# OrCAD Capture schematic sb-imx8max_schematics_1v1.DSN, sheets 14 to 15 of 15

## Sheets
14 08. UART,RS232,RS485, EEPROM,SD: size C; title: 08. UART,RS232,RS485, EEPROM,SD; note: 8010055003
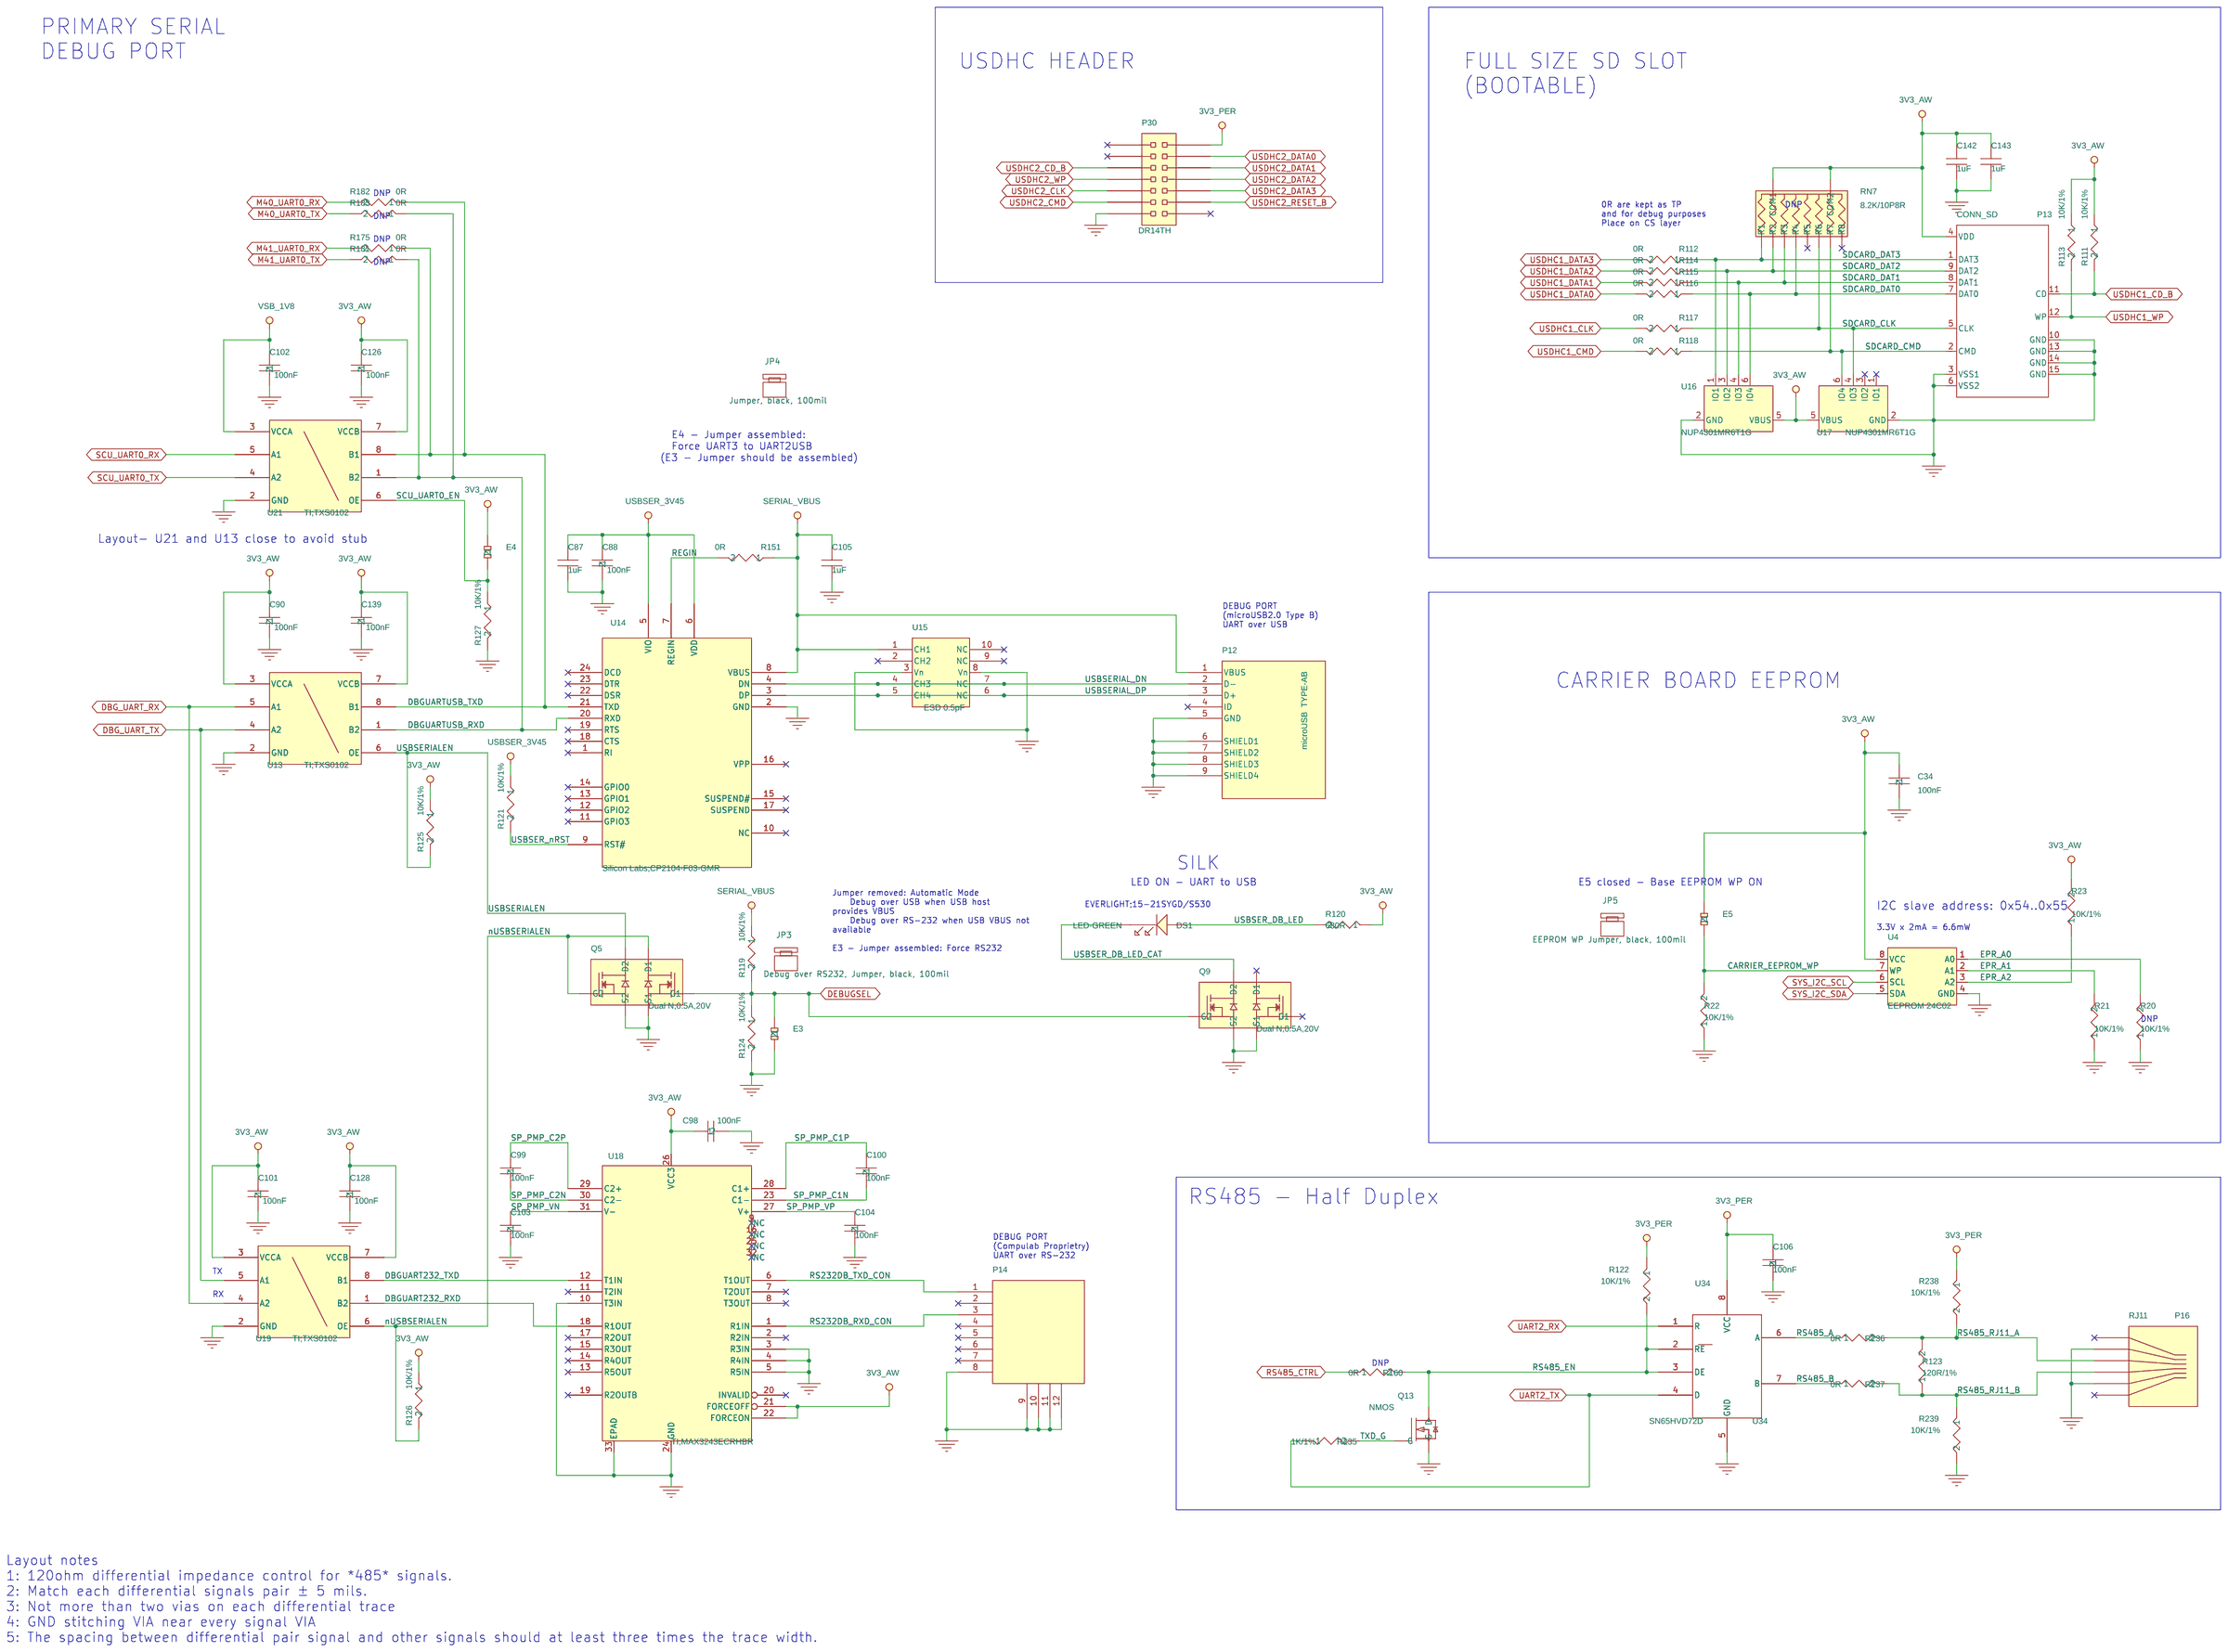
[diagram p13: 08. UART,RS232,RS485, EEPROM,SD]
15 09. POWER: size B; title: 09. POWER; note: 8010055003
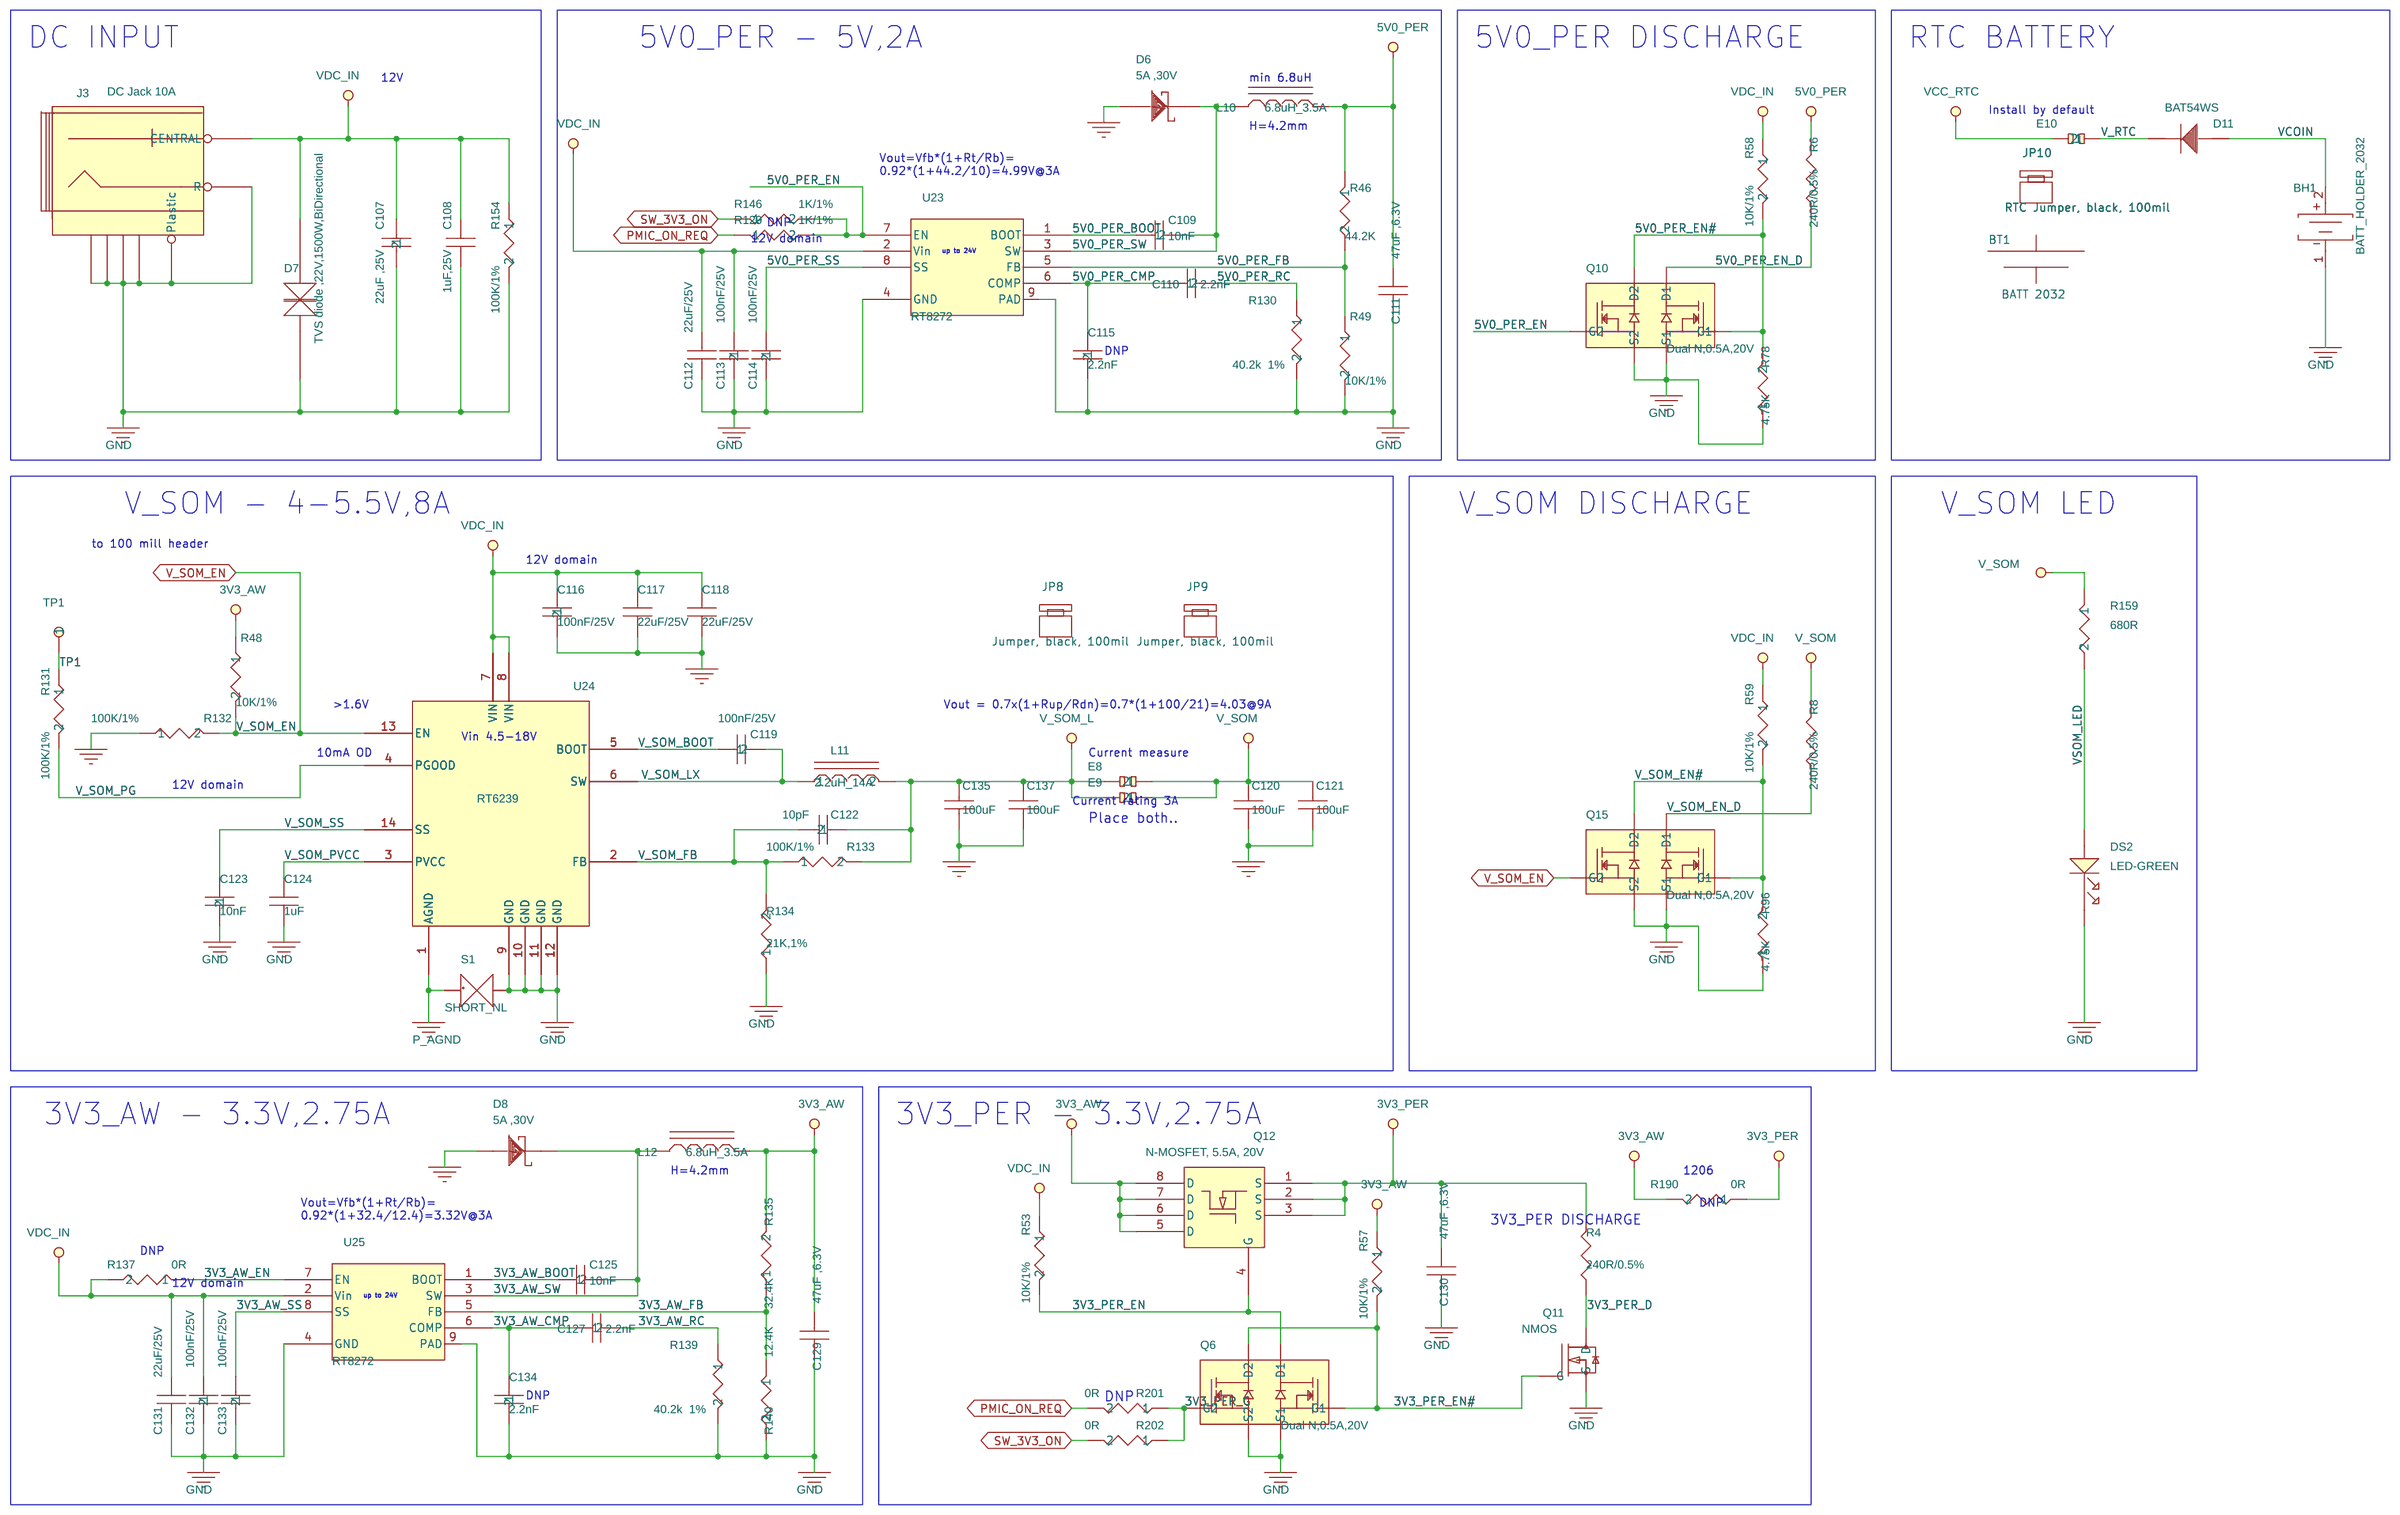
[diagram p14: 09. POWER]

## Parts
sheet 08. UART,RS232,RS485, EEPROM,SD
C34  100nF  [RC0402]
C87  1uF  [RC0402]
C88  100nF  [RC0402]
C90  100nF  [RC0402]
C98  100nF  [RC0402]
C99  100nF  [RC0402]
C100  100nF  [RC0402]
C101  100nF  [RC0402]
C102  100nF  [RC0402]
C103  100nF  [RC0402]
C104  100nF  [RC0402]
C105  1uF  [RC0402]
C106  100nF  [RC0402]
C126  100nF  [RC0402]
C128  100nF  [RC0402]
C139  100nF  [RC0402]
C142  1uF  [RC0402]
C143  1uF  [RC0402]
DS1  LED-GREEN  [LED-1206]
E3  HDR1X2  [1X2THHDR]
E4  HDR1X2  [1X2THHDR]
E5  HDR1X2  [1X2THHDR]
JP3  Debug over RS232, Jumper, black, 100mil
JP4  Jumper, black, 100mil
JP5  EEPROM WP Jumper, black, 100mil
P12  microUSB  TYPE-AB  [MICRO-USB-AB-RA-SM]
P13  CONN_SD  [SD-RA-SM]
P14  Ultra Mini Serial Connector  [UMS-8]
P16  RJ11  [RJ11TH6-6]
P30  DR14TH  [2X7THHDR]
Q5  Dual N,0.5A,20V  [SOT-563-6]
Q9  Dual N,0.5A,20V  [SOT-563-6]
Q13  NMOS  [SOT23]
R20  10K/1%  [RC0402]
R21  10K/1%  [RC0402]
R22  10K/1%  [RC0402]
R23  10K/1%  [RC0402]
R111  10K/1%  [RC0402]
R112  0R  [RC0402]
R113  10K/1%  [RC0402]
R114  0R  [RC0402]
R115  0R  [RC0402]
R116  0R  [RC0402]
R117  0R  [RC0402]
R118  0R  [RC0402]
R119  10K/1%  [RC0402]
R120  680R  [RC0402]
R121  10K/1%  [RC0402]
R122  10K/1%  [RC0402]
R123  120R/1%  [RC0603]
R124  10K/1%  [RC0402]
R125  10K/1%  [RC0402]
R126  10K/1%  [RC0402]
R127  10K/1%  [RC0402]
R151  0R  [RC0402]
R160  0R  [RC0402]
R175  0R  [RC0402]
R181  0R  [RC0402]
R182  0R  [RC0402]
R183  0R  [RC0402]
R235  1K/1%  [RC0402]
R236  0R  [RC0402]
R237  0R  [RC0402]
R238  10K/1%  [RC0402]
R239  10K/1%  [RC0402]
RN7  8.2K/10P8R  [RESNET10P1206]
U4  EEPROM 24C02  [MO-229VCED-2]
U13  TI;TXS0102  [MO-187DA-8]
U14  Silicon Labs;CP2104-F03-GMR  [MO-220VGGD-8]
U15  ESD 0.5pF  [DFN-X2510D-10]
U16  NUP4301MR6T1G  [SOT23-6L]
U17  NUP4301MR6T1G  [SOT23-6L]
U18  TI;MAX3243ECRHBR  [QFN5x5-32]
U19  TI;TXS0102  [MO-187DA-8]
U21  TI;TXS0102  [MO-187DA-8]
U34  SN65HVD72D  [MSOP-8]
sheet 09. POWER
BH1  BATT_HOLDER_2032  [BATTH20MM]
BT1  BATT 2032
C107  22uF ,25V  [C1210H1_9]
C108  1uF,25V  [RC0402]
C109  10nF  [RC0402]
C110  2.2nF  [RC0402]
C111  47uF ,6.3V  [C0805]
C112  22uF/25V  [C0805]
C113  100nF/25V  [RC0402]
C114  100nF/25V  [RC0402]
C115  2.2nF  [RC0402]
C116  100nF/25V  [RC0402]
C117  22uF/25V  [C0805]
C118  22uF/25V  [C0805]
C119  100nF/25V  [RC0402]
C120  100uF  [C1210H2_5]
C121  100uF  [C1210H2_5]
C122  10pF  [RC0402]
C123  10nF  [RC0402]
C124  1uF  [RC0402]
C125  10nF  [RC0402]
C127  2.2nF  [RC0402]
C129  47uF ,6.3V  [C0805]
C130  47uF ,6.3V  [C0805]
C131  22uF/25V  [C0805]
C132  100nF/25V  [RC0402]
C133  100nF/25V  [RC0402]
C134  2.2nF  [RC0402]
C135  100uF  [C1210H2_5]
C137  100uF  [C1210H2_5]
D6  5A ,30V  [SOD-128]
D7  TVS diode ,22V,1500W,BiDirectional  [DO-214AB]
D8  5A ,30V  [SOD-128]
D11  BAT54WS  [SOD-323]
DS2  LED-GREEN  [LED-1206]
E8  HDR1X2  [1X2THHDR]
E9  HDR1X2  [1X2THHDR]
E10  HDR1X2  [1X2THHDR]
J3  DC Jack 10A  [PJ-0810-TH]
JP8  Jumper, black, 100mil
JP9  Jumper, black, 100mil
JP10  RTC Jumper, black, 100mil
L10  6.8uH_3.5A  [IND8_2x8_2]
L11  2.2uH_14A  [IND7x7_2SM]
L12  6.8uH_3.5A  [IND8_2x8_2]
Q6  Dual N,0.5A,20V  [SOT-563-6]
Q10  Dual N,0.5A,20V  [SOT-563-6]
Q11  NMOS  [SOT23]
Q12  N-MOSFET, 5.5A, 20V  [PowerpakSO-8]
Q15  Dual N,0.5A,20V  [SOT-563-6]
R4  240R/0.5%  [RC0402]
R6  240R/0.5%  [RC0402]
R8  240R/0.5%  [RC0402]
R46  44.2K  [RC0402]
R48  10K/1%  [RC0402]
R49  10K/1%  [RC0402]
R53  10K/1%  [RC0402]
R57  10K/1%  [RC0402]
R58  10K/1%  [RC0402]
R59  10K/1%  [RC0402]
R78  4.75K  [RC0402]
R96  4.75K  [RC0402]
R129  1K/1%  [RC0402]
R130  40.2k  1%  [RC0402]
R131  100K/1%  [RC0402]
R132  100K/1%  [RC0402]
R133  100K/1%  [RC0402]
R134  21K,1%  [RC0402]
R135  32.4K  [RC0402]
R137  0R  [RC0402]
R139  40.2k  1%  [RC0402]
R140  12.4K  [RC0402]
R146  1K/1%  [RC0402]
R154  100K/1%  [RC0402]
R159  680R  [RC0402]
R190  0R  [RC1206]
R201  0R  [RC0402]
R202  0R  [RC0402]
S1  SHORT_NL  [SHORT_NL]
TP1  TESTPOINT  [TESTPOINT]
U23  RT8272  [PSOP-8-2X2]
U24  RT6239  [uQFN2x3-14]
U25  RT8272  [PSOP-8-2X2]

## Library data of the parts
C34 = 100nF,_10V,_X7R,_10%,_0402_5: CLABCONF0: SB-iMX8MAX
C87 C105 C142 C143 = 1uF,X5R,6.3V,0402: CLABCONF0: SB-iMX8MAX
C88 = 100nF,_10V,_X7R,_10%,_0402_12: CLABCONF0: SB-iMX8MAX
C90 = 100nF,_10V,_X7R,_10%,_0402_3: CLABCONF0: SB-iMX8MAX
C98 = 100nF,_10V,_X7R,_10%,_0402_2: CLABCONF0: SB-iMX8MAX
C99 = 100nF,_10V,_X7R,_10%,_0402_9: CLABCONF0: SB-iMX8MAX
C100 = 100nF,_10V,_X7R,_10%,_0402_4: CLABCONF0: SB-iMX8MAX
C101 = 100nF,_10V,_X7R,_10%,_0402_7: CLABCONF0: SB-iMX8MAX
C102 = 100nF,_10V,_X7R,_10%,_0402_8: CLABCONF0: SB-iMX8MAX
C103 = 100nF,_10V,_X7R,_10%,_0402: CLABCONF0: SB-iMX8MAX
C104 = 100nF,_10V,_X7R,_10%,_0402_6: CLABCONF0: SB-iMX8MAX
C106 = 100nF,_10V,_X7R,_10%,_0402_13: CLABCONF0: SB-iMX8MAX
C126 = 100nF,_10V,_X7R,_10%,_0402_10: CLABCONF0: SB-iMX8MAX
C128 = 100nF,_10V,_X7R,_10%,_0402_11: CLABCONF0: SB-iMX8MAX
C139 = 100nF,_10V,_X7R,_10%,_0402_1: CLABCONF0: SB-iMX8MAX
DS1 DS2 = LED-GREEN_1206_3: CLABCONF0: SB-iMX8MAX
E3 E9 = HDR_1x2_100MIL_TH_JUMPER_2: CLABCONF0: SB-iMX8MAX
E4 E10 = HDR_1x2_100MIL_TH_JUMPER_1: CLABCONF0: SB-iMX8MAX
E5 E8 = HDR_1x2_100MIL_TH_JUMPER: CLABCONF0: SB-iMX8MAX
JP3-JP5 JP8 JP9 = Jumper,_black,_100mil_0: CLABCONF0: SB-iMX8MAX
P12 = Conn.,_Micro-USB,_B-Type: CLABCONF0: SB-iMX8MAX; P/N: 180K00501S
P13 = SDIO_SLOT: CLABCONF0: SB-iMX8MAX
P14 = Ultra_Mini_Serial_Connector: CLABCONF0: SB-iMX8MAX
P16 = RJ11: CLABCONF0: SB-iMX8MAX
P30 = HDR_2x7_100MIL_TH: CLABCONF0: SB-iMX8MAX; P/N: 190C01402
Q5 Q6 Q9 Q10 Q15 = DUAL_N-MOSFET,_0.5A_20V: CLABCONF0: SB-iMX8MAX
Q11 Q13 = N-MOSFET,NDS335N,100mOhm@2.5V: CLABCONF0: SB-iMX8MAX
R20 = 10K,1%,0402,1_16W_14: CLABCONF0: DNP
R21 = 10K,1%,0402,1_16W_8: CLABCONF0: SB-iMX8MAX
R22 = 10K,1%,0402,1_16W_12: CLABCONF0: SB-iMX8MAX
R23 = 10K,1%,0402,1_16W_10: CLABCONF0: SB-iMX8MAX
R111 = 10K,1%,0402,1_16W_11: CLABCONF0: SB-iMX8MAX
R112 = 0R,_0402_1_11: CLABCONF0: SB-iMX8MAX
R59 R113 = 10K,1%,0402,1_16W_5: CLABCONF0: SB-iMX8MAX
R114 = 0R,_0402_1_8: CLABCONF0: SB-iMX8MAX
R115 R202 = 0R,_0402_1: CLABCONF0: SB-iMX8MAX
R116 = 0R,_0402_1_4: CLABCONF0: SB-iMX8MAX
R117 = 0R,_0402_1_3: CLABCONF0: SB-iMX8MAX
R118 = 0R,_0402_1_9: CLABCONF0: SB-iMX8MAX
R48 R119 = 10K,1%,0402,1_16W: CLABCONF0: SB-iMX8MAX
R120 R159 = 47K,_0402: CLABCONF0: SB-iMX8MAX; P/N: 161C68001S
R49 R121 = 10K,1%,0402,1_16W_1: CLABCONF0: SB-iMX8MAX
R57 R122 = 10K,1%,0402,1_16W_2: CLABCONF0: SB-iMX8MAX
R123 = 120R_1%,_0603: CLABCONF0: SB-iMX8MAX
R58 R124 = 10K,1%,0402,1_16W_3: CLABCONF0: SB-iMX8MAX
R125 = 10K,1%,0402,1_16W_9: CLABCONF0: SB-iMX8MAX
R126 = 10K,1%,0402,1_16W_15: CLABCONF0: SB-iMX8MAX
R127 = 10K,1%,0402,1_16W_6: CLABCONF0: SB-iMX8MAX
R151 = 0R,_0402_1_6: CLABCONF0: SB-iMX8MAX
R137 R160 = 0R,_0402_1_2: CLABCONF0: DNP
R175 = 0R,_0402_1_5: CLABCONF0: DNP
R181 = 0R,_0402_1_7: CLABCONF0: DNP
R182 = 0R,_0402_1_10: CLABCONF0: DNP
R183 = 0R,_0402_1_12: CLABCONF0: DNP
R235 = 10K,1%,0402,1_16W_13: CLABCONF0: SB-iMX8MAX; P/N: 161C10011S
R236 = 0R,_0402_1_13: CLABCONF0: SB-iMX8MAX
R237 = 0R,_0402_1_1: CLABCONF0: SB-iMX8MAX
R53 R238 = 10K,1%,0402,1_16W_4: CLABCONF0: SB-iMX8MAX
R239 = 10K,1%,0402,1_16W_7: CLABCONF0: SB-iMX8MAX
RN7 = RN,8.2K,10P8R@1206: CLABCONF0: DNP
U4 = 24C02,_serial_EE,_2KB,_I2C: CLABCONF0: SB-iMX8MAX; P/N: 111S30801S
U13 U19 U21 = TXS0102_0: CLABCONF0: SB-iMX8MAX; P/N: 116A01020S
U14 = CP2104_0: CLABCONF0: SB-iMX8MAX; P/N: 116A00140S
U15 = IC,ESD_Diode,0.25pF_,x4: CLABCONF0: SB-iMX8MAX; P/N: 132D10020S
U16 U17 = IP4220CZ6_0: CLABCONF0: SB-iMX8MAX
U18 = MAX3243E_RS-232_3T5R_BGA: CLABCONF0: SB-iMX8MAX
U34 = SN65HVD72D_1: CLABCONF0: SB-iMX8MAX; P/N: 116A00310S; PN: 116A00310S
BH1 = BATT_HOLDER_0: CLABCONF0: SB-iMX8MAX
BT1 = BATT_2032: CLABCONF0: SB-iMX8MAX
C107 = Cap.,_47uF,_16V,_X5R: CLABCONF0: SB-iMX8MAX; P/N: 151C22620S
C108 = 1uF,16V,0402: CLABCONF0: SB-iMX8MAX; P/N: 151C10501S
C109 = 10nF,_25V,_X7R,_10%,_0402_2: CLABCONF0: SB-iMX8MAX
C110 = 2.2nF,_50V,_X7R,_10%,_0402_3: CLABCONF0: SB-iMX8MAX
C111 = 47uF,6.3V,X5R: CLABCONF0: SB-iMX8MAX
C112 = Cap.,22uF,25V,_0805_1: CLABCONF0: SB-iMX8MAX
C113 = 100nF_0402_25V_2: CLABCONF0: SB-iMX8MAX
C114 = 100nF_0402_25V: CLABCONF0: SB-iMX8MAX
C115 = 2.2nF,_50V,_X7R,_10%,_0402: CLABCONF0: DNP
C116 = 100nF_0402_25V_5: CLABCONF0: SB-iMX8MAX
C117 = 22uF,25V,_0805_1: CLABCONF0: SB-iMX8MAX
C118 = 22uF,25V,_0805: CLABCONF0: SB-iMX8MAX
C119 = 100nF_0402_25V_4: CLABCONF0: SB-iMX8MAX
C120 C121 C135 C137 = 100uF,_6.3V,_X5R,_20%,_1206: CLABCONF0: SB-iMX8MAX
C122 = 10pF,50V,NPO,_5%,_0402: CLABCONF0: SB-iMX8MAX
C123 = 10nF,_25V,_X7R,_10%,_0402: CLABCONF0: SB-iMX8MAX
C124 = 1uF,16V,0402: CLABCONF0: SB-iMX8MAX
C125 = 10nF,_25V,_X7R,_10%,_0402_1: CLABCONF0: SB-iMX8MAX
C127 = 2.2nF,_50V,_X7R,_10%,_0402_1: CLABCONF0: SB-iMX8MAX
C129 = 47uF,6.3V,X5R_1: CLABCONF0: SB-iMX8MAX
C130 = 47uF,6.3V,X5R_2: CLABCONF0: SB-iMX8MAX
C131 = Cap.,22uF,25V,_0805: CLABCONF0: SB-iMX8MAX
C132 = 100nF_0402_25V_1: CLABCONF0: SB-iMX8MAX
C133 = 100nF_0402_25V_3: CLABCONF0: SB-iMX8MAX
C134 = 2.2nF,_50V,_X7R,_10%,_0402_2: CLABCONF0: DNP
D6 D8 = Diode_Shotky,5A,30V: CLABCONF0: SB-iMX8MAX
D7 = Diode_,TVS_,15V,1500W_1: CLABCONF0: SB-iMX8MAX; P/N: 132D10030S
D11 = BAT54WS_0: CLABCONF0: SB-iMX8MAX
J3 = DC_Jack_,5.5_2_0.5,10A,20V: CLABCONF0: SB-iMX8MAX
JP10 = Jumper,_black,_100mil: CLABCONF0: SB-iMX8MAX
L10 L12 = IND_6.8uH_3.5A: CLABCONF0: SB-iMX8MAX; P/N: 147A6R801S
L11 = IND_DELTA_MPL73-2R2_2.2uH_14A: CLABCONF0: SB-iMX8MAX
Q12 = N-MOSFET_5_0.5A_@20V_Vgs: CLABCONF0: SB-iMX8MAX
R4 = 240R_resistor,_%0.5: CLABCONF0: SB-iMX8MAX; P/N: 161C24003S
R6 = 240R_resistor,_%0.5_1: CLABCONF0: SB-iMX8MAX; P/N: 161C24003S
R8 = 240R_resistor,_%0.5_2: CLABCONF0: SB-iMX8MAX; P/N: 161C24003S
R46 = 100K,_0402: CLABCONF0: SB-iMX8MAX; P/N: 161C44221S
R78 = 4_0.75K,1%,0402,1_16W_1: CLABCONF0: SB-iMX8MAX
R96 = 4_0.75K,1%,0402,1_16W: CLABCONF0: SB-iMX8MAX
R129 = 1K,1%,0402,1_16W: CLABCONF0: DNP; Group: CAN
R130 = 40.2k_,1%: CLABCONF0: SB-iMX8MAX
R131 = 100K,_1%,_0402,_1_16W: CLABCONF0: SB-iMX8MAX
R132 = 100K,_1%,_0402,_1_16W_3: CLABCONF0: SB-iMX8MAX
R133 = 100K,_1%,_0402,_1_16W_1: CLABCONF0: SB-iMX8MAX
R134 = 43.2K,1%,0402: CLABCONF0: SB-iMX8MAX; P/N: 161C21021S
R135 = 32.4K,_0402: CLABCONF0: SB-iMX8MAX; P/N: 161C32421S
R139 = 40.2k_,1%_1: CLABCONF0: SB-iMX8MAX
R140 = 4.99K,1%,0402,1_16W: CLABCONF0: SB-iMX8MAX; P/N: 161C12421S
R146 = 1K,1%,0402,1_16W_1: CLABCONF0: SB-iMX8MAX; Group: CAN
R154 = 100K,_1%,_0402,_1_16W_2: CLABCONF0: SB-iMX8MAX
R190 = 0R,_1206: CLABCONF0: DNP
R201 = 0R,_0402_1_1: CLABCONF0: DNP
S1 = MISC_SHORT_NL: CLABCONF0: SB-iMX8MAX
TP1 = TESTPOINT: CLABCONF0: SB-iMX8MAX
U23 U25 = RT8272,Converter,3A,24V: CLABCONF0: SB-iMX8MAX
U24 = RT6239A_B: CLABCONF0: SB-iMX8MAX; P/N: 123V08000S

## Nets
3V3_AW: C34.1 C90.1 C98.1 C101.1 C126.1 C128.1 C129.1 C139.1 C142.1 C143.1 E4.1 E5.1 L12.2 P13.4(VDD) Q12.5(D) Q12.6(D) Q12.7(D) Q12.8(D) R23.2 R48.1 R57.1 R111.1 R113.1 R120.1 R125.1 R126.1 R135.2 R190.2 RN7.5(COM1) RN7.10(COM2) U4.8(VCC) U13.3(VCCA) U13.7(VCCB) U16.5(VBUS) U17.5(VBUS) U18.21(FORCEOFF) U18.22(FORCEON) U18.26(VCC3) U19.3(VCCA) U19.7(VCCB) U21.7(VCCB) ; also on sheet 5 9 11 12 13
3V3_AW_BOOT: C125.1 U25.1(BOOT)
3V3_AW_CMP: C127.1 C134.1 U25.6(COMP)
3V3_AW_EN: R137.1 U25.7(EN)
3V3_AW_FB: R135.1 R140.1 U25.5(FB)
3V3_AW_RC: C127.2 R139.1
3V3_AW_SS: C133.1 U25.8(SS)
3V3_AW_SW: C125.2 D8.CATHODE L12.1 U25.3(SW)
3V3_PER: C106.1 C130.1 P30.2 Q12.1(S) Q12.2(S) Q12.3(S) R4.1 R122.1 R190.1 R238.1 U34.8(VCC) ; also on sheet 1 2 3 4 5 6 9 11 12 13
3V3_PER_D: Q11.3(D) R4.2
3V3_PER_EN: Q6.6(D1) Q12.4(G) R53.2
3V3_PER_EN#: Q6.2(G1) Q6.3(D2) Q11.1(G) R57.2
3V3_PER_G: Q6.5(G2) R201.1 R202.1
5V0_PER: C111.1 L10.2 R6.1 R46.1 ; also on sheet 1 4 9 11 12 13
5V0_PER_BOOT: C109.1 U23.1(BOOT)
5V0_PER_CMP: C110.1 C115.1 U23.6(COMP)
5V0_PER_EN: Q10.5(G2) R129.2 R146.2 U23.7(EN)
5V0_PER_EN#: Q10.2(G1) Q10.3(D2) R58.2 R78.2
5V0_PER_EN_D: Q10.6(D1) R6.2
5V0_PER_FB: R46.2 R49.1 U23.5(FB)
5V0_PER_RC: C110.2 R130.1
5V0_PER_SS: C114.1 U23.8(SS)
5V0_PER_SW: C109.2 D6.CATHODE L10.1 U23.3(SW)
GND: BH1.1(MINUS) C34.2 C87.2 C88.2 C90.2 C98.2 C101.2 C102.2 C103.2 C104.2 C105.2 C106.2 C107.2 C108.2 C111.2 C112.2 C113.2 C114.2 C115.2 C116.2 C117.2 C118.2 C120.1 C121.1 C123.2 C124.2 C126.2 C128.2 C129.2 C130.2 C131.2 C132.2 C133.2 C134.2 C135.1 C137.1 C139.2 C142.2 C143.2 D6.ANODE D7.ANODE D8.ANODE DS2.CATHODE E3.2 J3.2(R) J3.3(Plastic) J3.SH1 J3.SH2 J3.SH3 J3.SH4 P12.5(GND) P12.6(SHIELD1) P12.7(SHIELD2) P12.8(SHIELD3) P12.9(SHIELD4) P13.3(VSS1) P13.6(VSS2) P13.10(GND) P13.13(GND) P13.14(GND) P13.15(GND) P14.8 P14.9(CHASSIS) P14.10(CHASSIS) P14.11(CHASSIS) P14.12(CHASSIS) P16.2 P16.5 P30.13 Q5.1(S1) Q5.4(S2) Q6.1(S1) Q6.4(S2) Q9.1(S1) Q9.4(S2) Q10.1(S1) Q10.4(S2) Q11.2(S) Q13.2(S) Q15.1(S1) Q15.4(S2) R20.1 R21.1 R22.1 R49.2 R78.1 R96.1 R124.2 R127.2 R130.2 R132.1 R134.1 R139.2 R140.2 R154.2 R239.2 S1.2 U4.4(GND) U13.2(GND) U14.2(GND) U15.3(Vn) U15.8(Vn) U16.2(GND) U17.2(GND) U18.3(R3IN) U18.4(R4IN) U18.5(R5IN) U18.10(T3IN) U18.24(GND) U18.33(EPAD) U19.2(GND) U21.2(GND) U23.4(GND) U23.9(PAD) U24.9(GND) U24.10(GND) U24.11(GND) U24.12(GND) U25.4(GND) U25.9(PAD) U34.5(GND) ; also on sheet 1 2 3 4 5 6 7 9 10 11 12 13
VCC_RTC: E10.2 ; also on sheet 9
CARRIER_EEPROM_WP: E5.2 R22.2 U4.7(WP)
DBG_UART_RX: U13.5(A1) U19.4(A2) ; also on sheet 9
DBG_UART_TX: U13.4(A2) U19.5(A1) ; also on sheet 9
DBGUART232_RXD: U18.18(R1OUT) U19.1(B2)
DBGUART232_TXD: U18.12(T1IN) U19.8(B1)
DBGUARTUSB_RXD: R181.1 R183.1 U13.1(B2) U14.20(RXD) U21.1(B2)
DBGUARTUSB_TXD: R175.1 R182.1 U13.8(B1) U14.21(TXD) U21.8(B1)
DEBUGSEL: E3.1 Q5.2(G1) Q9.5(G2) R119.2 R124.1 ; also on sheet 13
EPR_A0: R20.2 U4.1(A0)
EPR_A1: R21.2 U4.2(A1)
EPR_A2: R23.1 U4.3(A2)
M40_UART0_RX: R182.2 ; also on sheet 9
M40_UART0_TX: R183.2 ; also on sheet 9
M41_UART0_RX: R175.2 ; also on sheet 9
M41_UART0_TX: R181.2 ; also on sheet 9
nUSBSERIALEN: Q5.5(G2) Q5.6(D1) R126.2 U19.6(OE)
P_AGND: S1.1 U24.1(AGND)
PMIC_ON_REQ: R129.1 R201.2 ; also on sheet 9 12 13
REGIN: R151.2 U14.7(REGIN)
RS232DB_RXD_CON: P14.3 U18.1(R1IN)
RS232DB_TXD_CON: P14.1 U18.6(T1OUT)
RS485_A: R236.1 U34.6(A)
RS485_B: R237.1 U34.7(B)
RS485_CTRL: R160.1 ; also on sheet 13
RS485_EN: Q13.3(D) R122.2 R160.2 U34.2(RE) U34.3(DE)
RS485_RJ11_A: P16.3 R123.2 R236.2 R238.2
RS485_RJ11_B: P16.4 R123.1 R237.2 R239.1
SCU_UART0_EN: E4.2 R127.1 U21.6(OE)
SCU_UART0_RX: U21.5(A1) ; also on sheet 9 12
SCU_UART0_TX: U21.4(A2) ; also on sheet 9 12
SDCARD_CLK: P13.5(CLK) R117.1 RN7.7(R6) U17.4(IO3)
SDCARD_CMD: P13.2(CMD) R118.1 RN7.8(R7) U17.6(IO4)
SDCARD_DAT0: P13.7(DAT0) R116.1 RN7.4(R4) U16.6(IO4)
SDCARD_DAT1: P13.8(DAT1) R115.1 RN7.3(R3) U16.4(IO3)
SDCARD_DAT2: P13.9(DAT2) R114.1 RN7.2(R2) U16.3(IO2)
SDCARD_DAT3: P13.1(DAT3) R112.1 RN7.1(R1) U16.1(IO1)
SERIAL_VBUS: C105.1 P12.1(VBUS) R119.1 R151.1 U14.8(VBUS) U15.1(CH1)
SP_PMP_C1N: C100.2 U18.23(C1-)
SP_PMP_C1P: C100.1 U18.28(C1+)
SP_PMP_C2N: C99.2 U18.30(C2-)
SP_PMP_C2P: C99.1 U18.29(C2+)
SP_PMP_VN: C103.1 U18.31(V-)
SP_PMP_VP: C104.1 U18.27(V+)
SW_3V3_ON: R146.1 R202.2 ; also on sheet 9
SYS_I2C_SCL: U4.6(SCL) ; also on sheet 2 5 9 11 13
SYS_I2C_SDA: U4.5(SDA) ; also on sheet 2 5 9 11 13
TP1: R131.1 TP1.1
TXD_G: Q13.1(G) R235.2
UART2_RX: U34.1(R) ; also on sheet 9
UART2_TX: R235.1 U34.4(D) ; also on sheet 9
USBSER_3V45: C87.1 C88.1 R121.1 U14.5(VIO) U14.6(VDD)
USBSER_DB_LED: DS1.ANODE R120.2
USBSER_DB_LED_CAT: DS1.CATHODE Q9.3(D2)
USBSER_nRST: R121.2 U14.9(RST#)
USBSERIAL_DN: P12.2(D-) U14.4(DN) U15.4(CH3) U15.7(NC)
USBSERIAL_DP: P12.3(D+) U14.3(DP) U15.5(CH4) U15.6(NC)
USBSERIALEN: Q5.3(D2) R125.2 U13.6(OE)
USDHC1_CD_B: P13.11(CD) R111.2 ; also on sheet 9
USDHC1_CLK: R117.2 ; also on sheet 9
USDHC1_CMD: R118.2 ; also on sheet 9
USDHC1_DATA0: R116.2 ; also on sheet 9
USDHC1_DATA1: R115.2 ; also on sheet 9
USDHC1_DATA2: R114.2 ; also on sheet 9
USDHC1_DATA3: R112.2 ; also on sheet 9
USDHC1_WP: P13.12(WP) R113.2 ; also on sheet 9
USDHC2_CD_B: P30.5 ; also on sheet 9
USDHC2_CLK: P30.9 ; also on sheet 9
USDHC2_CMD: P30.11 ; also on sheet 9
USDHC2_DATA0: P30.4 ; also on sheet 9
USDHC2_DATA1: P30.6 ; also on sheet 9
USDHC2_DATA2: P30.8 ; also on sheet 9
USDHC2_DATA3: P30.10 ; also on sheet 9
USDHC2_RESET_B: P30.12 ; also on sheet 9 12
USDHC2_WP: P30.7 ; also on sheet 9
V_RTC: D11.CATHODE E10.1
V_SOM: C120.2 C121.2 E8.1 E9.1 R8.1 R159.1 ; also on sheet 3 6 9 13
V_SOM_BOOT: C119.1 U24.5(BOOT)
V_SOM_EN: Q15.5(G2) R48.2 R132.2 U24.13(EN) ; also on sheet 12
V_SOM_EN#: Q15.2(G1) Q15.3(D2) R59.2 R96.2
V_SOM_EN_D: Q15.6(D1) R8.2
V_SOM_FB: C122.2 R133.1 R134.2 U24.2(FB)
V_SOM_L: C122.1 C135.2 C137.2 E8.2 E9.2 L11.2 R133.2
V_SOM_LX: C119.2 L11.1 U24.6(SW)
V_SOM_PG: R131.2 U24.4(PGOOD)
V_SOM_PVCC: C124.1 U24.3(PVCC)
V_SOM_SS: C123.1 U24.14(SS)
VCOIN: BH1.2(PLUS) D11.ANODE
VDC_IN: C107.1 C108.1 C112.1 C113.1 C116.1 C117.1 C118.1 C131.1 C132.1 D7.CATHODE J3.1(CENTRAL) R53.1 R58.1 R59.1 R137.2 R154.1 U23.2(Vin) U24.7(VIN) U24.8(VIN) U25.2(Vin) ; also on sheet 5
VSB_1V8: C102.1 U21.3(VCCA) ; also on sheet 3 6 9 12 13
VSOM_LED: DS2.ANODE R159.2

Not connected (* = marked no-connect by the designer): P12 4(ID)*; P14 2* 4* 5* 6* 7*; P16 1* 6*; P30 1* 3* 14*; Q9 2(G1)* 6(D1)*; RN7 6(R5)* 9(R8)*; U14 1(RI)* 10(NC)* 11(GPIO3)* 12(GPIO2)* 13(GPIO1)* 14(GPIO0)* 15(SUSPEND#)* 16(VPP)* 17(SUSPEND)* 18(CTS)* 19(RTS)* 22(DSR)* 23(DTR)* 24(DCD)*; U15 2(CH2)* 9(NC)* 10(NC)*; U17 1(IO1)* 3(IO2)*; U18 2(R2IN)* 7(T2OUT)* 8(T3OUT)* 9(NC)* 11(T2IN)* 13(R5OUT)* 14(R4OUT)* 15(R3OUT)* 16(NC)* 17(R2OUT)* 19(R2OUTB)* 20(INVALID)* 25(NC)* 32(NC)*

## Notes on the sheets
sheet 14
- PRIMARY SERIAL
  DEBUG PORT
- USDHC HEADER
- FULL SIZE SD SLOT
  (BOOTABLE)
- DNP
- 0R are kept as TP
  and for debug purposes
  Place on CS layer
- DNP
- DNP
- DNP
- DNP
- E4 - Jumper assembled:
- Force UART3 to UART2USB
- (E3 - Jumper should be assembled)
- Layout- U21 and U13 close to avoid stub
- DEBUG PORT
  (microUSB2.0 Type B)
  UART over USB
- CARRIER BOARD EEPROM
- SILK
- LED ON - UART to USB
- E5 closed - Base EEPROM WP ON
- Jumper removed: Automatic Mode
      Debug over USB when USB host
  provides VBUS
      Debug over RS-232 when USB VBUS not
  available
  E3 - Jumper assembled: Force RS232
- EVERLIGHT;15-21SYGD/S530
- I2C slave address: 0x54..0x55
- 3.3V x 2mA = 6.6mW
- DNP
- RS485 - Half Duplex
- DEBUG PORT
  (Compulab Proprietry)
  UART over RS-232
- TX
- RX
- DNP
- Layout notes
  1: 120ohm differential impedance control for *485* signals.
  2: Match each differential signals pair ± 5 mils.
  3: Not more than two vias on each differential trace
  4: GND stitching VIA near every signal VIA
  5: The spacing between differential pair signal and other signals should at least three times the trace width.
sheet 15
- DC INPUT
- 5V0_PER - 5V,2A
- 5V0_PER DISCHARGE
- RTC BATTERY
- 12V
- min 6.8uH
- Install by default
- H=4.2mm
- Vout=Vfb*(1+Rt/Rb)=
  0.92*(1+44.2/10)=4.99V@3A
- DNP
- 12V domain
- up to 24V
- DNP
- V_SOM - 4-5.5V,8A
- V_SOM DISCHARGE
- V_SOM LED
- to 100 mill header
- 12V domain
- >1.6V
- Vout = 0.7x(1+Rup/Rdn)=0.7*(1+100/21)=4.03@9A
- Vin 4.5-18V
- 10mA OD
- Current measure
- 12V domain
- Current rating 3A
- Place both..
- 3V3_AW - 3.3V,2.75A
- 3V3_PER - 3.3V,2.75A
- H=4.2mm
- 1206
- Vout=Vfb*(1+Rt/Rb)=
  0.92*(1+32.4/12.4)=3.32V@3A
- DNP
- 3V3_PER DISCHARGE
- DNP
- 12V domain
- up to 24V
- DNP
- DNP
